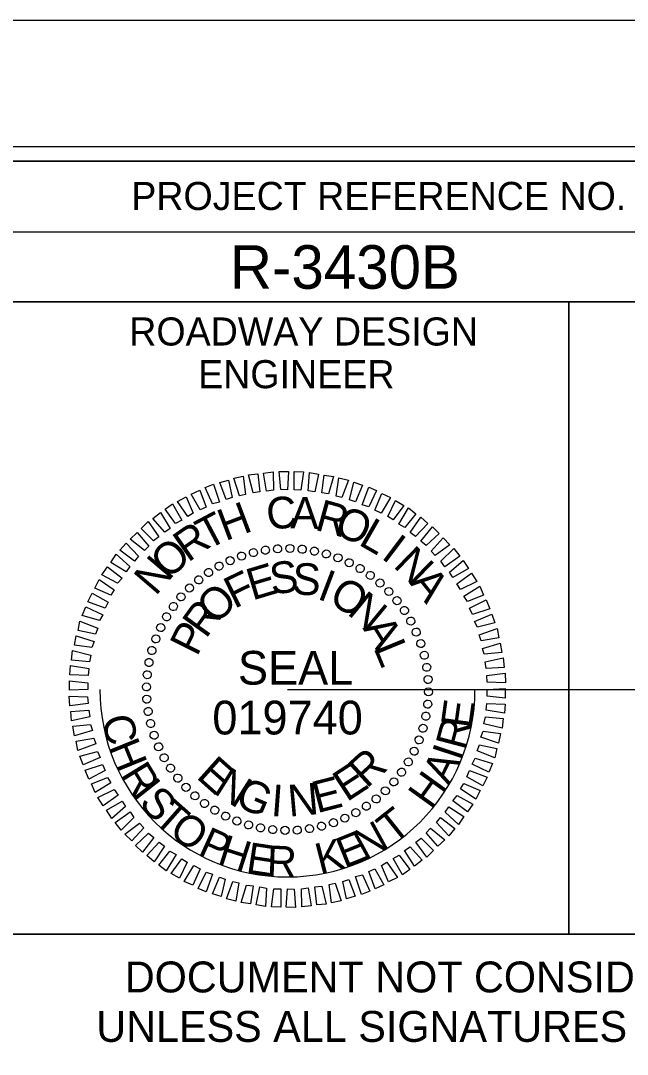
# Model space of a CAD drawing. Extents: x 1260439 to 1262228, y 742196 to 743296.
# Drawn here: x 1261908.3 to 1262016.2, y 743111.8 to 743295.7 of the extents above; entities that cross this region are included whole.
import ezdxf

# ---------------------------------------------------------------- set-up
doc = ezdxf.new("R2010")
doc.units = 0
for name, color, linetype in [('Scratch_Level_0', 7, 'Continuous'), ('Scratch_Level_1', 7, 'Continuous'), ('Sheet Cutting Line CELL', 7, 'Continuous'), ('Sheet Data Field CELL', 7, 'Continuous'), ('Sheet Plot Border Inside CELL', 7, 'Continuous'), ('Sheet Plot Border Outside CELL', 7, 'Continuous'), ('Sheet Professional Seal CELL', 7, 'Continuous'), ('Sheet Profile CELL', 7, 'Continuous'), ('Sheet Sticker Exception Certification CELL', 7, 'Continuous')]:
    doc.layers.add(name, color=color, linetype=linetype)

msp = doc.modelspace()

# ---------------------------------------------------------------- linework, layer by layer
at = {"layer": 'Scratch_Level_0'}
msp.add_arc((1261955.7, 743176.75), 33.36, 180, 360, dxfattribs=at)
at = {"layer": 'Scratch_Level_1'}
for q in [(1262228.23, 743176.75), (1261955.7, 743176.75)]:
    msp.add_line((1261955.7, 743176.75), q, dxfattribs=at)
at = {"layer": 'Sheet Cutting Line CELL'}
msp.add_line((1262122.75, 743295.74), (1260438.75, 743295.74), dxfattribs=at)
at = {"layer": 'Sheet Plot Border Inside CELL'}
msp.add_lwpolyline([(1260451.75, 742218.19), (1262118.25, 742218.19), (1262118.25, 743273.29), (1260451.75, 743273.29)], close=True, dxfattribs=at)
at = {"layer": 'Sheet Plot Border Outside CELL'}
msp.add_lwpolyline([(1260438.75, 742195.74), (1262122.75, 742195.74), (1262122.75, 743295.74), (1260438.75, 743295.74)], close=True, dxfattribs=at)
at = {"layer": 'Sheet Professional Seal CELL'}
for p, q in [((1261947.5, 743200.5), (1261947.5, 743200.5)), ((1261949.6, 743201.1), (1261949.6, 743201.1)), ((1261951.8, 743201.5), (1261951.8, 743201.5)), ((1261953.95, 743201.8), (1261953.95, 743201.8)), ((1261956.15, 743201.85), (1261956.15, 743201.85)), ((1261958.35, 743201.7), (1261958.35, 743201.7)), ((1261960.5, 743201.35), (1261960.5, 743201.35)), ((1261962.6, 743200.9), (1261962.6, 743200.9)), ((1261964.7, 743200.2), (1261964.7, 743200.2)), ((1261943.55, 743198.7), (1261943.55, 743198.7)), ((1261945.5, 743199.7), (1261945.5, 743199.7)), ((1261966.7, 743199.3), (1261966.7, 743199.3)), ((1261941.65, 743197.55), (1261941.65, 743197.55)), ((1261968.65, 743198.3), (1261968.65, 743198.3)), ((1261970.45, 743197.05), (1261970.45, 743197.05)), ((1261938.25, 743194.8), (1261938.25, 743194.8)), ((1261939.9, 743196.3), (1261939.9, 743196.3)), ((1261972.2, 743195.7), (1261972.2, 743195.7)), ((1261936.75, 743193.25), (1261936.75, 743193.25)), ((1261973.75, 743194.2), (1261973.75, 743194.2)), ((1261935.4, 743191.5), (1261935.4, 743191.5)), ((1261975.25, 743192.55), (1261975.25, 743192.55)), ((1261934.15, 743189.7), (1261934.15, 743189.7)), ((1261976.5, 743190.8), (1261976.5, 743190.8)), ((1261933.15, 743187.75), (1261933.15, 743187.75)), ((1261977.65, 743188.9), (1261977.65, 743188.9)), ((1261932.25, 743185.75), (1261932.25, 743185.75)), ((1261978.65, 743186.95), (1261978.65, 743186.95)), ((1261931.55, 743183.65), (1261931.55, 743183.65)), ((1261979.45, 743184.95), (1261979.45, 743184.95)), ((1261980.05, 743182.85), (1261980.05, 743182.85)), ((1261931.1, 743181.55), (1261931.1, 743181.55)), ((1261980.45, 743180.65), (1261980.45, 743180.65)), ((1261930.75, 743179.4), (1261930.75, 743179.4)), ((1261980.75, 743178.5), (1261980.75, 743178.5)), ((1261930.6, 743177.2), (1261930.6, 743177.2)), ((1261955.7, 743176.75), (1261955.7, 743176.75)), ((1261980.8, 743176.3), (1261980.8, 743176.3)), ((1261930.65, 743175), (1261930.65, 743175)), ((1261930.95, 743172.85), (1261930.95, 743172.85)), ((1261980.65, 743174.1), (1261980.65, 743174.1)), ((1261980.3, 743171.95), (1261980.3, 743171.95)), ((1261931.35, 743170.65), (1261931.35, 743170.65)), ((1261979.85, 743169.85), (1261979.85, 743169.85)), ((1261931.95, 743168.55), (1261931.95, 743168.55)), ((1261979.15, 743167.75), (1261979.15, 743167.75)), ((1261932.75, 743166.55), (1261932.75, 743166.55)), ((1261978.25, 743165.75), (1261978.25, 743165.75)), ((1261933.75, 743164.6), (1261933.75, 743164.6)), ((1261977.25, 743163.8), (1261977.25, 743163.8)), ((1261934.9, 743162.7), (1261934.9, 743162.7)), ((1261976, 743162), (1261976, 743162)), ((1261936.15, 743160.95), (1261936.15, 743160.95)), ((1261974.65, 743160.25), (1261974.65, 743160.25)), ((1261937.65, 743159.3), (1261937.65, 743159.3)), ((1261973.15, 743158.7), (1261973.15, 743158.7)), ((1261939.2, 743157.8), (1261939.2, 743157.8)), ((1261940.95, 743156.45), (1261940.95, 743156.45)), ((1261971.5, 743157.2), (1261971.5, 743157.2)), ((1261942.75, 743155.2), (1261942.75, 743155.2)), ((1261944.7, 743154.2), (1261944.7, 743154.2)), ((1261967.85, 743154.8), (1261967.85, 743154.8)), ((1261969.75, 743155.95), (1261969.75, 743155.95)), ((1261946.7, 743153.3), (1261946.7, 743153.3)), ((1261948.8, 743152.6), (1261948.8, 743152.6)), ((1261961.8, 743152.4), (1261961.8, 743152.4)), ((1261963.9, 743153), (1261963.9, 743153)), ((1261965.9, 743153.8), (1261965.9, 743153.8)), ((1261950.9, 743152.15), (1261950.9, 743152.15)), ((1261953.05, 743151.8), (1261953.05, 743151.8)), ((1261955.25, 743151.65), (1261955.25, 743151.65)), ((1261957.45, 743151.7), (1261957.45, 743151.7)), ((1261959.6, 743152), (1261959.6, 743152))]:
    msp.add_line(p, q, dxfattribs=at)
for points in [[(1261949.6, 743211.75), (1261948.8, 743214.95), (1261950.45, 743215.1), (1261950.8, 743211.9)], [(1261952, 743212.05), (1261951.45, 743215.25), (1261953.15, 743215.45), (1261953.2, 743212.2)], [(1261954.5, 743212.3), (1261954.25, 743215.55), (1261955.9, 743215.5), (1261955.7, 743212.25)], [(1261956.9, 743212.25), (1261956.9, 743215.5), (1261958.55, 743215.45), (1261958.1, 743212.2)], [(1261959.4, 743212.1), (1261959.6, 743215.35), (1261961.25, 743215.05), (1261960.6, 743211.9)], [(1261961.8, 743211.7), (1261962.25, 743214.9), (1261963.9, 743214.65), (1261963, 743211.55)], [(1261942.35, 743209.75), (1261941.05, 743212.65), (1261942.55, 743213.25), (1261943.6, 743210.05)], [(1261944.8, 743210.55), (1261943.65, 743213.55), (1261945.2, 743214), (1261945.85, 743210.9)], [(1261947.2, 743211.2), (1261946.15, 743214.35), (1261947.85, 743214.7), (1261948.25, 743211.45)], [(1261964.35, 743211.15), (1261964.85, 743214.4), (1261966.55, 743214), (1261965.4, 743210.9)], [(1261966.75, 743210.5), (1261967.5, 743213.6), (1261969.05, 743213.1), (1261967.8, 743210.15)], [(1261940.15, 743208.7), (1261938.55, 743211.5), (1261940.1, 743212.2), (1261941.25, 743209.15)], [(1261969, 743209.6), (1261970.15, 743212.75), (1261971.55, 743212.15), (1261970.15, 743209.25)], [(1261971.25, 743208.65), (1261972.5, 743211.6), (1261974.05, 743210.9), (1261972.35, 743208.1)], [(1261935.8, 743206.25), (1261933.95, 743208.8), (1261935.25, 743209.75), (1261936.9, 743206.85)], [(1261938, 743207.5), (1261936.15, 743210.2), (1261937.7, 743211), (1261938.95, 743208.1)], [(1261973.55, 743207.5), (1261974.9, 743210.35), (1261976.4, 743209.5), (1261974.5, 743206.9)], [(1261933.9, 743204.75), (1261931.75, 743207.15), (1261933.1, 743208.2), (1261934.85, 743205.4)], [(1261975.5, 743206.15), (1261977.25, 743209.05), (1261978.55, 743208), (1261976.6, 743205.55)], [(1261931.9, 743203.2), (1261929.7, 743205.4), (1261930.9, 743206.6), (1261932.85, 743203.9)], [(1261977.55, 743204.65), (1261979.4, 743207.4), (1261980.7, 743206.3), (1261978.5, 743203.95)], [(1261979.45, 743203.1), (1261981.5, 743205.7), (1261982.7, 743204.5), (1261980.4, 743202.35)], [(1261930.25, 743201.45), (1261927.7, 743203.5), (1261928.95, 743204.65), (1261931.05, 743202.25)], [(1261928.5, 743199.55), (1261925.9, 743201.5), (1261927, 743202.8), (1261929.2, 743200.45)], [(1261981.25, 743201.35), (1261983.4, 743203.7), (1261984.6, 743202.5), (1261982, 743200.55)], [(1261927, 743197.65), (1261924.3, 743199.35), (1261925.25, 743200.8), (1261927.65, 743198.6)], [(1261983, 743199.55), (1261985.3, 743201.8), (1261986.35, 743200.45), (1261983.7, 743198.55)], [(1261925.5, 743195.65), (1261922.7, 743197.15), (1261923.7, 743198.55), (1261926.3, 743196.55)], [(1261984.5, 743197.6), (1261986.95, 743199.7), (1261987.9, 743198.25), (1261985.1, 743196.65)], [(1261985.8, 743195.55), (1261988.45, 743197.45), (1261989.4, 743195.95), (1261986.5, 743194.55)], [(1261924.3, 743193.5), (1261921.45, 743194.75), (1261922.2, 743196.3), (1261924.9, 743194.45)], [(1261987.1, 743193.35), (1261989.9, 743195.1), (1261990.55, 743193.55), (1261987.7, 743192.4)], [(1261923.3, 743191.2), (1261920.2, 743192.35), (1261920.95, 743193.9), (1261923.8, 743192.3)], [(1261922.3, 743189), (1261919.2, 743189.9), (1261919.85, 743191.45), (1261922.85, 743190.05)], [(1261988.1, 743191.2), (1261991.05, 743192.7), (1261991.7, 743191.1), (1261988.6, 743190.1)], [(1261989, 743188.85), (1261992.05, 743190.15), (1261992.6, 743188.6), (1261989.5, 743187.8)], [(1261921.55, 743186.6), (1261918.45, 743187.25), (1261918.8, 743188.9), (1261921.95, 743187.65)], [(1261989.8, 743186.45), (1261993, 743187.6), (1261993.3, 743185.95), (1261990.15, 743185.4)], [(1261920.9, 743184.2), (1261917.8, 743184.6), (1261918.15, 743186.3), (1261921.3, 743185.25)], [(1261920.5, 743181.65), (1261917.3, 743181.95), (1261917.5, 743183.65), (1261920.75, 743182.85)], [(1261990.4, 743184.05), (1261993.55, 743185), (1261993.85, 743183.3), (1261990.7, 743183)], [(1261990.85, 743181.65), (1261994.1, 743182.35), (1261994.25, 743180.65), (1261991.05, 743180.45)], [(1261920.25, 743179.25), (1261917, 743179.35), (1261917.1, 743181), (1261920.35, 743180.45)], [(1261920.2, 743176.75), (1261916.95, 743176.6), (1261916.95, 743178.3), (1261920.2, 743177.95)], [(1261991.15, 743179.25), (1261994.4, 743179.65), (1261994.5, 743177.95), (1261991.25, 743178.05)], [(1261991.2, 743176.75), (1261994.45, 743176.9), (1261994.45, 743175.2), (1261991.2, 743175.55)], [(1261920.25, 743174.25), (1261917, 743173.85), (1261916.9, 743175.55), (1261920.15, 743175.45)], [(1261920.55, 743171.85), (1261917.3, 743171.15), (1261917.15, 743172.85), (1261920.35, 743173.05)], [(1261991.15, 743174.25), (1261994.4, 743174.15), (1261994.3, 743172.5), (1261991.05, 743173.05)], [(1261990.9, 743171.85), (1261994.1, 743171.55), (1261993.9, 743169.85), (1261990.65, 743170.65)], [(1261921, 743169.45), (1261917.85, 743168.5), (1261917.55, 743170.2), (1261920.7, 743170.5)], [(1261990.5, 743169.3), (1261993.6, 743168.9), (1261993.25, 743167.2), (1261990.1, 743168.25)], [(1261921.6, 743167.05), (1261918.4, 743165.9), (1261918.1, 743167.55), (1261921.25, 743168.1)], [(1261922.4, 743164.65), (1261919.35, 743163.35), (1261918.8, 743164.9), (1261921.9, 743165.7)], [(1261989.85, 743166.9), (1261992.95, 743166.25), (1261992.6, 743164.6), (1261989.45, 743165.85)], [(1261923.3, 743162.3), (1261920.35, 743160.8), (1261919.7, 743162.4), (1261922.8, 743163.4)], [(1261989.1, 743164.5), (1261992.2, 743163.6), (1261991.55, 743162.05), (1261988.55, 743163.45)], [(1261988.1, 743162.3), (1261991.2, 743161.15), (1261990.45, 743159.6), (1261987.6, 743161.2)], [(1261924.3, 743160.15), (1261921.5, 743158.4), (1261920.85, 743159.95), (1261923.7, 743161.1)], [(1261987.1, 743160), (1261989.95, 743158.75), (1261989.2, 743157.2), (1261986.5, 743159.05)], [(1261925.6, 743157.95), (1261922.95, 743156.05), (1261922, 743157.55), (1261924.9, 743158.95)], [(1261926.9, 743155.9), (1261924.45, 743153.8), (1261923.5, 743155.25), (1261926.3, 743156.85)], [(1261985.9, 743157.85), (1261988.7, 743156.35), (1261987.7, 743154.95), (1261985.1, 743156.95)], [(1261928.4, 743153.95), (1261926.1, 743151.7), (1261925.05, 743153.05), (1261927.7, 743154.95)], [(1261984.4, 743155.85), (1261987.1, 743154.15), (1261986.15, 743152.7), (1261983.75, 743154.9)], [(1261930.15, 743152.15), (1261928, 743149.8), (1261926.8, 743151), (1261929.4, 743152.95)], [(1261982.9, 743153.95), (1261985.5, 743152), (1261984.4, 743150.7), (1261982.2, 743153.05)], [(1261931.95, 743150.4), (1261929.9, 743147.8), (1261928.7, 743149), (1261931, 743151.15)], [(1261981.15, 743152.05), (1261983.7, 743150), (1261982.45, 743148.85), (1261980.35, 743151.25)], [(1261933.85, 743148.85), (1261932, 743146.1), (1261930.7, 743147.2), (1261932.9, 743149.55)], [(1261977.5, 743148.75), (1261979.65, 743146.35), (1261978.3, 743145.3), (1261976.55, 743148.1)], [(1261979.5, 743150.3), (1261981.7, 743148.1), (1261980.5, 743146.9), (1261978.55, 743149.6)], [(1261935.9, 743147.35), (1261934.15, 743144.45), (1261932.85, 743145.5), (1261934.8, 743147.95)], [(1261975.6, 743147.25), (1261977.45, 743144.7), (1261976.15, 743143.75), (1261974.5, 743146.65)], [(1261937.85, 743146), (1261936.5, 743143.15), (1261935, 743144), (1261936.9, 743146.6)], [(1261940.15, 743144.85), (1261938.9, 743141.9), (1261937.35, 743142.6), (1261939.05, 743145.4)], [(1261973.4, 743146), (1261975.25, 743143.3), (1261973.7, 743142.5), (1261972.45, 743145.4)], [(1261942.4, 743143.9), (1261941.25, 743140.75), (1261939.85, 743141.35), (1261941.25, 743144.25)], [(1261944.65, 743143), (1261943.9, 743139.9), (1261942.35, 743140.4), (1261943.6, 743143.35)], [(1261969.05, 743143.75), (1261970.35, 743140.85), (1261968.85, 743140.25), (1261967.8, 743143.45)], [(1261971.25, 743144.8), (1261972.85, 743142), (1261971.3, 743141.3), (1261970.15, 743144.35)], [(1261947.05, 743142.35), (1261946.55, 743139.1), (1261944.85, 743139.5), (1261946, 743142.6)], [(1261949.6, 743141.8), (1261949.15, 743138.6), (1261947.5, 743138.85), (1261948.4, 743141.95)], [(1261952, 743141.4), (1261951.8, 743138.15), (1261950.15, 743138.45), (1261950.8, 743141.6)], [(1261959.4, 743141.45), (1261959.95, 743138.25), (1261958.25, 743138.05), (1261958.2, 743141.3)], [(1261961.8, 743141.75), (1261962.6, 743138.55), (1261960.95, 743138.4), (1261960.6, 743141.6)], [(1261964.2, 743142.3), (1261965.25, 743139.15), (1261963.55, 743138.8), (1261963.15, 743142.05)], [(1261966.6, 743142.95), (1261967.75, 743139.95), (1261966.2, 743139.5), (1261965.55, 743142.6)], [(1261954.5, 743141.25), (1261954.5, 743138), (1261952.85, 743138.05), (1261953.3, 743141.3)], [(1261956.9, 743141.2), (1261957.15, 743137.95), (1261955.5, 743138), (1261955.7, 743141.25)]]:
    msp.add_lwpolyline(points, close=True, dxfattribs=at)
for centre, major_axis in [((1261951.78, 743201.52), (-0.113, 0.711)), ((1261953.95, 743201.77), (-0.05, 0.718)), ((1261956.14, 743201.83), (0.013, 0.72)), ((1261958.32, 743201.7), (0.075, 0.716)), ((1261960.49, 743201.37), (0.137, 0.707)), ((1261945.5, 743199.66), (-0.293, 0.658)), ((1261947.54, 743200.47), (-0.234, 0.681)), ((1261949.64, 743201.09), (-0.174, 0.699)), ((1261962.62, 743200.86), (0.198, 0.692)), ((1261964.69, 743200.17), (0.258, 0.672)), ((1261941.68, 743197.55), (-0.403, 0.597)), ((1261943.54, 743198.69), (-0.349, 0.63)), ((1261966.7, 743199.29), (0.316, 0.647)), ((1261968.62, 743198.25), (0.371, 0.617)), ((1261939.92, 743196.24), (-0.453, 0.56)), ((1261970.44, 743197.04), (0.423, 0.582)), ((1261938.28, 743194.79), (-0.5, 0.518)), ((1261972.16, 743195.68), (0.472, 0.543)), ((1261973.74, 743194.17), (0.518, 0.5)), ((1261936.77, 743193.21), (-0.543, 0.472)), ((1261975.19, 743192.54), (0.56, 0.453)), ((1261935.41, 743191.49), (-0.582, 0.423)), ((1261976.5, 743190.78), (0.597, 0.403)), ((1261934.21, 743189.67), (-0.617, 0.371)), ((1261977.64, 743188.91), (0.63, 0.349)), ((1261933.16, 743187.75), (-0.647, 0.316)), ((1261978.61, 743186.95), (0.658, 0.293)), ((1261932.29, 743185.74), (-0.672, 0.258)), ((1261979.42, 743184.92), (0.681, 0.234)), ((1261931.59, 743183.67), (-0.692, 0.198)), ((1261980.04, 743182.82), (0.699, 0.174)), ((1261931.08, 743181.54), (-0.707, 0.137)), ((1261930.76, 743179.37), (-0.716, 0.075)), ((1261980.47, 743180.68), (0.711, 0.113)), ((1261980.72, 743178.5), (0.718, 0.05)), ((1261930.63, 743177.19), (-0.72, 0.013)), ((1261980.78, 743176.32), (0.72, -0.013)), ((1261930.68, 743175), (-0.718, -0.05)), ((1261980.65, 743174.13), (0.716, -0.075)), ((1261930.93, 743172.83), (-0.711, -0.113)), ((1261980.32, 743171.97), (0.707, -0.137)), ((1261931.37, 743170.69), (-0.699, -0.174)), ((1261931.99, 743168.59), (-0.681, -0.234)), ((1261979.81, 743169.84), (0.692, -0.198)), ((1261932.79, 743166.55), (-0.658, -0.293)), ((1261979.12, 743167.76), (0.672, -0.258)), ((1261933.77, 743164.59), (-0.63, -0.349)), ((1261978.24, 743165.76), (0.647, -0.316)), ((1261934.91, 743162.73), (-0.597, -0.403)), ((1261977.2, 743163.84), (0.617, -0.371)), ((1261936.21, 743160.97), (-0.56, -0.453)), ((1261975.99, 743162.01), (0.582, -0.423)), ((1261937.66, 743159.33), (-0.518, -0.5)), ((1261974.63, 743160.3), (0.543, -0.472)), ((1261939.25, 743157.82), (-0.472, -0.543)), ((1261971.49, 743157.26), (0.453, -0.56)), ((1261973.12, 743158.71), (0.5, -0.518)), ((1261940.96, 743156.46), (-0.423, -0.582)), ((1261942.79, 743155.26), (-0.371, -0.617)), ((1261969.73, 743155.96), (0.403, -0.597)), ((1261944.71, 743154.21), (-0.316, -0.647)), ((1261965.9, 743153.84), (0.293, -0.658)), ((1261967.86, 743154.82), (0.349, -0.63)), ((1261946.71, 743153.34), (-0.258, -0.672)), ((1261948.79, 743152.64), (-0.198, -0.692)), ((1261950.92, 743152.13), (-0.137, -0.707)), ((1261953.08, 743151.81), (-0.075, -0.716)), ((1261955.27, 743151.68), (-0.013, -0.72)), ((1261957.45, 743151.73), (0.05, -0.718)), ((1261959.63, 743151.98), (0.113, -0.711)), ((1261961.77, 743152.42), (0.174, -0.699)), ((1261963.87, 743153.04), (0.234, -0.681))]:
    msp.add_ellipse(centre, major_axis=major_axis, ratio=0.999708, dxfattribs=at)
at = {"layer": 'Sheet Profile CELL'}
for p, q in [((1261905.7, 743258.19), (1262105.75, 743258.19)), ((1262005.75, 743245.69), (1262005.75, 743133.24))]:
    msp.add_line(p, q, dxfattribs=at)
for points in [[(1262105.75, 743270.74), (1260605.75, 743270.74), (1260605.75, 742220.74), (1262105.75, 742220.74)], [(1261905.7, 743270.74), (1262105.75, 743270.74), (1262105.75, 743245.69), (1261905.7, 743245.69)], [(1261905.7, 743245.69), (1262005.75, 743245.69), (1262005.75, 743133.19), (1261905.7, 743133.19)], [(1262005.75, 743245.69), (1262105.75, 743245.69), (1262105.75, 743133.19), (1262005.75, 743133.19)]]:
    msp.add_lwpolyline(points, close=True, dxfattribs=at)
at = {"layer": 'Sheet Sticker Exception Certification CELL'}
msp.add_line((1261905.7, 743133.19), (1262105.74, 743133.19), dxfattribs=at)

# ---------------------------------------------------------------- texts
at = {"layer": 'Sheet Data Field CELL'}
msp.add_text('R-3430B', height=7.75, dxfattribs=at).set_placement((1261945.47, 743248.04))
at = {"layer": 'Sheet Professional Seal CELL'}
for s, height, rotation, p in [('H', 5.64, 20.6195, (1261944.65, 743203.1)), ('C', 5.64, 6.2199, (1261952.25, 743205.1)), ('A', 5.64, 359.0203, (1261956.2, 743205.4)), ('R', 5.64, 344.6211, (1261960.4, 743205.2)), ('T', 5.64, 27.8198, (1261941.4, 743201.45)), ('O', 5.64, 337.4212, (1261963.75, 743204.45)), ('R', 5.64, 35.0205, (1261938, 743199.25)), ('L', 5.64, 330.2209, (1261968.15, 743202.6)), ('I', 5.64, 323.0201, (1261972.2, 743200.2)), ('O', 5.64, 42.2217, (1261934.55, 743196.15)), ('N', 5.64, 315.8189, (1261974.35, 743198.65)), ('N', 5.64, 49.4235, (1261932.25, 743193.25)), ('E', 5.64, 16.6111, (1261949.45, 743192.55)), ('S', 5.64, 7.2556, (1261952.9, 743193.6)), ('S', 5.64, 357.9004, (1261956.5, 743193.65)), ('F', 5.64, 25.967, (1261946.25, 743191.05)), ('I', 5.64, 339.1896, (1261960.8, 743192.95)), ('A', 5.64, 308.6172, (1261977.3, 743195.7)), ('O', 5.64, 44.6812, (1261942.95, 743188.1)), ('O', 5.64, 329.8335, (1261962.8, 743192.25)), ('N', 5.64, 320.4766, (1261966.15, 743190.25)), ('R', 5.64, 54.0397, (1261941.2, 743185.65)), ('P', 5.64, 63.3989, (1261939.6, 743182.45)), ('A', 5.64, 301.7603, (1261969, 743187.65)), ('L', 5.64, 292.4008, (1261970.95, 743184.2)), ('SEAL', 5.998, 360, (1261946.9, 743177.6)), ('019740', 5.998, 360, (1261942.34, 743168.74)), ('E', 5.5, 82.1825, (1261988.41, 743169.66)), ('C', 5.5, 283.2464, (1261922.63, 743171.62)), ('R', 5.5, 75.2561, (1261987.31, 743165.76)), ('H', 5.5, 292.1191, (1261923.82, 743166.58)), ('R', 5.64, 42.4814, (1261969.8, 743159)), ('I', 5.5, 71.7356, (1261986.58, 743163.84)), ('R', 5.5, 301.3639, (1261925.87, 743161.59)), ('E', 5.64, 318.2769, (1261939.3, 743161.1)), ('E', 5.64, 33.1241, (1261966.25, 743156.65)), ('A', 5.5, 63.5498, (1261984.42, 743159.58)), ('N', 5.64, 327.634, (1261942.3, 743158.4)), ('H', 5.5, 54.305, (1261981.29, 743155.19)), ('I', 5.5, 308.2904, (1261927.92, 743158.11)), ('G', 5.64, 336.9902, (1261946.1, 743156.15)), ('I', 5.64, 355.7012, (1261952.65, 743154.25)), ('N', 5.64, 5.0564, (1261956, 743154.1)), ('E', 5.64, 14.4118, (1261960.95, 743154.7)), ('S', 5.5, 311.8108, (1261929.11, 743156.44)), ('T', 5.5, 318.5942, (1261931.7, 743153.44)), ('T', 5.5, 38.5631, (1261974.48, 743149.05)), ('O', 5.5, 324.8909, (1261934.4, 743150.94)), ('N', 5.5, 28.6314, (1261969.42, 743146.23)), ('P', 5.5, 335.5954, (1261939.57, 743147.44)), ('H', 5.5, 342.1784, (1261943.03, 743145.78)), ('E', 5.5, 22.0484, (1261965.83, 743144.86)), ('E', 5.5, 351.4232, (1261948.17, 743144.15)), ('R', 5.5, 358.0062, (1261951.96, 743143.5)), ('K', 5.5, 14.3778, (1261961.49, 743143.79))]:
    msp.add_text(s, height=height, rotation=rotation, dxfattribs=at).set_placement(p)
at = {"layer": 'Sheet Profile CELL'}
for s, height, p in [('PROJECT REFERENCE NO.', 5.0001, (1261927.92, 743262.05)), ('ROADWAY DESIGN', 5.0001, (1261927.56, 743237.94)), ('ENGINEER', 5, (1261939.81, 743230.34))]:
    msp.add_text(s, height=height, dxfattribs=at).set_placement(p)
at = {"layer": 'Sheet Sticker Exception Certification CELL'}
for s, p in [('DOCUMENT NOT CONSIDERED FINAL', (1261926.78, 743122.84)), ('UNLESS ALL SIGNATURES COMPLETED', (1261921.7, 743114.04))]:
    msp.add_text(s, height=5.5, dxfattribs=at).set_placement(p)

doc.saveas('drawing.dxf')
